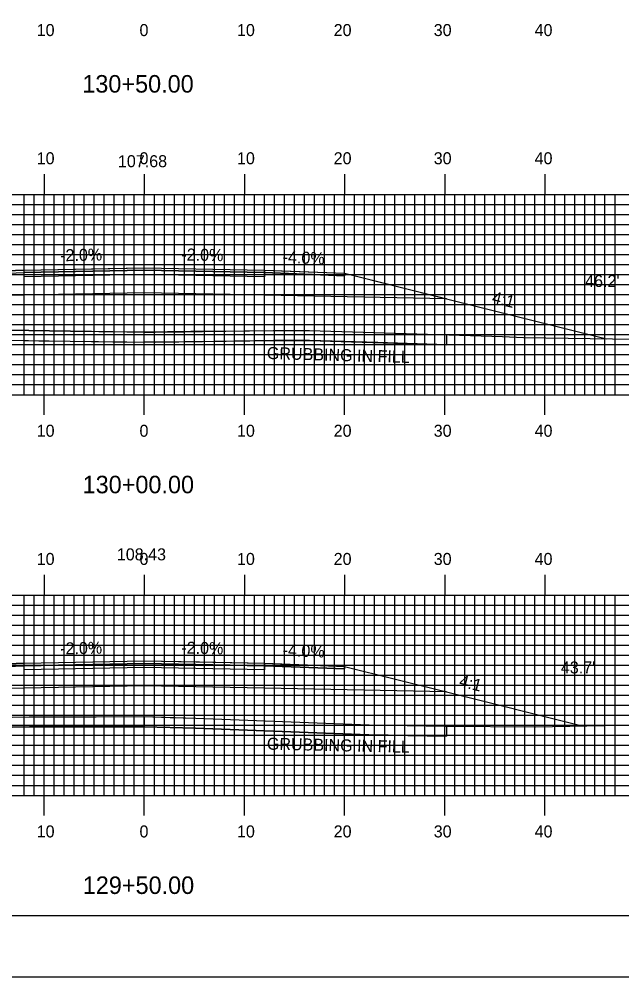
# Model space of a CAD drawing. Extents: x 1773990 to 1774333, y 442591 to 442811.
# Drawn here: x 1774143.2 to 1774203.3, y 442590.5 to 442686.2 of the extents above; entities that cross this region are included whole.
import ezdxf

# ---------------------------------------------------------------- set-up
doc = ezdxf.new("R2010")
doc.units = 0
for name, color, linetype in [('ANNOTATION', 7, 'Continuous'), ('BORDER', 7, 'Continuous'), ('D_Roadway_Centerline', 7, 'Continuous'), ('D_Roadway_Centerline_Text', 7, 'Continuous'), ('D_Roadway_Edge_Shoulder', 7, 'Continuous'), ('D_Roadway_Edge_TW', 7, 'Continuous'), ('D_Roadway_Pavement', 7, 'Continuous'), ('D_Roadway_SlopeLines', 7, 'Continuous'), ('D_Roadway_SubGrade', 7, 'Continuous'), ('D_Text_Standard', 7, 'Continuous'), ('GRUBBING IN FILL', 7, 'Continuous'), ('H_V ANNOTATION', 7, 'Continuous'), ('MAJOR', 7, 'Continuous'), ('MINOR', 7, 'Continuous'), ('PLOT BOUNDARY', 7, 'Continuous'), ('S_Roadway_Centerline', 7, 'Continuous')]:
    doc.layers.add(name, color=color, linetype=linetype)

msp = doc.modelspace()

# ---------------------------------------------------------------- linework, layer by layer
at = {"layer": 'BORDER'}
msp.add_lwpolyline([(1774006.059, 442596.665), (1774326.059, 442596.665), (1774326.059, 442806.665), (1774006.059, 442806.665)], close=True, dxfattribs=at)
at = {"layer": 'D_Roadway_Centerline'}
for points in [[(1774111.186, 442655.695), (1774121.01, 442658.151), (1774130.759, 442660.588), (1774143.659, 442661.104), (1774143.66, 442661.104), (1774152.062, 442661.272), (1774155.659, 442661.344), (1774167.659, 442661.104), (1774170.226, 442661.002), (1774175.659, 442660.784), (1774184.924, 442658.468), (1774185.833, 442658.24), (1774201.809, 442654.246), (1774201.81, 442654.246)], [(1774107.784, 442616.308), (1774117.905, 442618.838), (1774127.359, 442621.202), (1774143.659, 442621.854), (1774155.659, 442622.094), (1774161.174, 442621.984), (1774167.659, 442621.854), (1774171.953, 442621.682), (1774175.659, 442621.534), (1774185.833, 442618.99), (1774199.367, 442615.606)]]:
    msp.add_lwpolyline(points, dxfattribs=at)
at = {"layer": 'D_Roadway_Edge_Shoulder'}
for points in [[(1774143.659, 442661.104), (1774130.759, 442660.588), (1774130.759, 442660.338), (1774143.659, 442660.854)], [(1774167.659, 442661.104), (1774175.659, 442660.784), (1774175.659, 442660.534), (1774167.659, 442660.854)], [(1774143.659, 442621.854), (1774127.359, 442621.202), (1774127.359, 442620.952), (1774143.659, 442621.604)], [(1774167.659, 442621.854), (1774175.659, 442621.534), (1774175.659, 442621.284), (1774167.659, 442621.604)]]:
    msp.add_lwpolyline(points, close=True, dxfattribs=at)
at = {"layer": 'D_Roadway_Edge_TW'}
for points in [[(1774143.659, 442660.854), (1774143.659, 442661.104), (1774155.659, 442661.344), (1774167.659, 442661.104), (1774167.659, 442660.854), (1774155.659, 442661.094)], [(1774143.659, 442621.604), (1774143.659, 442621.854), (1774155.659, 442622.094), (1774167.659, 442621.854), (1774167.659, 442621.604), (1774155.659, 442621.844)]]:
    msp.add_lwpolyline(points, close=True, dxfattribs=at)
at = {"layer": 'D_Roadway_Pavement'}
for points in [[(1774143.659, 442660.437), (1774143.659, 442660.854), (1774155.659, 442661.094), (1774167.659, 442660.854), (1774167.659, 442660.437), (1774155.659, 442660.677)], [(1774143.659, 442621.187), (1774143.659, 442621.604), (1774155.659, 442621.844), (1774167.659, 442621.604), (1774167.659, 442621.187), (1774155.659, 442621.427)]]:
    msp.add_lwpolyline(points, close=True, dxfattribs=at)
at = {"layer": 'D_Roadway_SlopeLines'}
for points in [[(1774175.659, 442660.784), (1774185.833, 442658.24), (1774201.81, 442654.246)], [(1774175.659, 442621.534), (1774185.833, 442618.99), (1774199.367, 442615.606)]]:
    msp.add_lwpolyline(points, dxfattribs=at)
at = {"layer": 'D_Roadway_SubGrade'}
for points in [[(1774143.659, 442658.604), (1774121.01, 442658.151), (1774130.759, 442660.588), (1774130.759, 442660.338), (1774143.659, 442660.854), (1774155.659, 442661.094), (1774167.659, 442660.854), (1774175.659, 442660.534), (1774175.659, 442660.784), (1774185.833, 442658.24), (1774167.659, 442658.604), (1774155.659, 442658.844)], [(1774143.659, 442619.354), (1774117.905, 442618.838), (1774127.359, 442621.202), (1774127.359, 442620.952), (1774143.659, 442621.604), (1774155.659, 442621.844), (1774167.659, 442621.604), (1774175.659, 442621.284), (1774175.659, 442621.534), (1774185.833, 442618.99), (1774167.659, 442619.354), (1774155.659, 442619.594)]]:
    msp.add_lwpolyline(points, close=True, dxfattribs=at)
at = {"layer": 'GRUBBING IN FILL'}
for p, q in [((1774185.833, 442654.645), (1774185.833, 442653.644)), ((1774185.833, 442654.645), (1774185.833, 442653.644)), ((1774185.833, 442615.571), (1774185.833, 442614.569)), ((1774185.833, 442615.571), (1774185.833, 442614.569))]:
    msp.add_line(p, q, dxfattribs=at)
for points in [[(1774125.485, 442655.237), (1774125.485, 442654.211), (1774134.235, 442654.315), (1774138.123, 442654.206), (1774145.135, 442654.046), (1774148.26, 442653.994), (1774152.504, 442653.952), (1774155.659, 442653.921), (1774155.659, 442654.921), (1774152.509, 442654.952), (1774148.273, 442654.994), (1774142.032, 442655.097), (1774138.138, 442655.206), (1774134.243, 442655.315), (1774130.25, 442655.268), (1774126.257, 442655.22)], [(1774155.659, 442654.921), (1774156.746, 442654.91), (1774159.694, 442654.95), (1774162.642, 442654.99), (1774168.537, 442655.069), (1774172.16, 442655.082), (1774181.8, 442654.774), (1774185.833, 442654.645), (1774185.833, 442653.644), (1774178.988, 442653.863), (1774172.142, 442654.082), (1774168.548, 442654.069), (1774162.648, 442653.99), (1774156.748, 442653.91), (1774155.659, 442653.921)], [(1774155.659, 442654.921), (1774156.746, 442654.91), (1774159.694, 442654.95), (1774162.642, 442654.99), (1774168.537, 442655.069), (1774172.16, 442655.082), (1774181.8, 442654.774), (1774185.833, 442654.645), (1774185.833, 442653.644), (1774178.988, 442653.863), (1774172.142, 442654.082), (1774168.548, 442654.069), (1774162.648, 442653.99), (1774156.748, 442653.91), (1774155.659, 442653.921)], [(1774155.659, 442654.921), (1774156.746, 442654.91), (1774162.642, 442654.99)], [(1774155.659, 442654.921), (1774156.746, 442654.91), (1774162.642, 442654.99)], [(1774125.485, 442616.21), (1774132.101, 442616.307), (1774140.725, 442616.436), (1774144.174, 442616.491), (1774150.849, 442616.51), (1774155.659, 442616.523), (1774155.659, 442615.522), (1774150.852, 442615.51), (1774147.518, 442615.5), (1774144.183, 442615.491), (1774138.846, 442615.476), (1774134.703, 442615.344), (1774126.507, 442615.233), (1774125.485, 442615.21)], [(1774155.659, 442616.523), (1774158.25, 442616.443), (1774160.813, 442616.364), (1774169.463, 442616.039), (1774178.114, 442615.715), (1774185.833, 442615.571), (1774185.833, 442614.569), (1774181.959, 442614.642), (1774178.086, 442614.715), (1774169.432, 442615.04), (1774160.779, 442615.365), (1774155.659, 442615.522)], [(1774155.659, 442616.523), (1774158.25, 442616.443), (1774160.813, 442616.364), (1774169.463, 442616.039), (1774178.114, 442615.715), (1774185.833, 442615.571), (1774185.833, 442614.569), (1774181.959, 442614.642), (1774178.086, 442614.715), (1774169.432, 442615.04), (1774160.779, 442615.365), (1774155.659, 442615.522)]]:
    msp.add_lwpolyline(points, close=True, dxfattribs=at)
for points in [[(1774125.485, 442654.211), (1774134.235, 442654.315), (1774138.123, 442654.206), (1774145.135, 442654.046), (1774148.26, 442653.994), (1774152.504, 442653.952), (1774155.659, 442653.921), (1774155.659, 442654.921), (1774152.509, 442654.952), (1774148.273, 442654.994), (1774142.032, 442655.097), (1774138.138, 442655.206), (1774134.243, 442655.315), (1774130.25, 442655.268), (1774126.257, 442655.22), (1774125.485, 442655.237)], [(1774125.485, 442654.211), (1774134.235, 442654.315), (1774142.01, 442654.097), (1774148.26, 442653.994), (1774156.748, 442653.91), (1774168.548, 442654.069), (1774170.602, 442654.088), (1774172.142, 442654.082), (1774185.833, 442653.644)], [(1774125.485, 442654.211), (1774134.235, 442654.315), (1774142.01, 442654.097), (1774148.26, 442653.994), (1774156.748, 442653.91), (1774168.548, 442654.069), (1774170.602, 442654.088), (1774172.142, 442654.082), (1774185.833, 442653.644)], [(1774125.485, 442616.21), (1774132.101, 442616.307), (1774140.725, 442616.436), (1774144.174, 442616.491), (1774150.849, 442616.51), (1774155.659, 442616.523), (1774155.659, 442615.522), (1774150.852, 442615.51), (1774147.518, 442615.5), (1774144.183, 442615.491), (1774138.846, 442615.476), (1774134.703, 442615.344), (1774126.507, 442615.233), (1774125.485, 442615.21)], [(1774125.485, 442615.21), (1774127.529, 442615.255), (1774132.114, 442615.307), (1774137.292, 442615.382), (1774144.183, 442615.491), (1774150.852, 442615.51), (1774155.673, 442615.522), (1774160.779, 442615.365), (1774178.086, 442614.715), (1774185.833, 442614.569)], [(1774125.485, 442615.21), (1774127.529, 442615.255), (1774132.114, 442615.307), (1774137.292, 442615.382), (1774144.183, 442615.491), (1774150.852, 442615.51), (1774155.673, 442615.522), (1774160.779, 442615.365), (1774178.086, 442614.715), (1774185.833, 442614.569)]]:
    msp.add_lwpolyline(points, dxfattribs=at)
at = {"layer": 'MAJOR'}
for p, q in [((1774145.659, 442670.669), (1774145.659, 442668.665)), ((1774155.659, 442670.669), (1774155.659, 442668.665)), ((1774165.659, 442670.669), (1774165.659, 442668.665)), ((1774175.659, 442670.669), (1774175.659, 442668.665)), ((1774185.659, 442670.669), (1774185.659, 442668.665)), ((1774195.659, 442670.669), (1774195.659, 442668.665)), ((1774015.659, 442668.665), (1774295.659, 442668.665)), ((1774015.659, 442668.665), (1774295.659, 442668.665)), ((1774145.659, 442648.665), (1774145.659, 442668.665)), ((1774155.659, 442648.665), (1774155.659, 442668.665)), ((1774165.659, 442648.665), (1774165.659, 442668.665)), ((1774175.659, 442648.665), (1774175.659, 442668.665)), ((1774185.659, 442648.665), (1774185.659, 442668.665)), ((1774195.659, 442648.665), (1774195.659, 442668.665)), ((1774015.659, 442663.665), (1774295.659, 442663.665)), ((1774015.659, 442658.665), (1774295.659, 442658.665)), ((1774015.659, 442653.665), (1774295.659, 442653.665)), ((1774015.659, 442648.665), (1774295.659, 442648.665)), ((1774015.659, 442648.665), (1774295.659, 442648.665)), ((1774145.659, 442646.661), (1774145.659, 442648.665)), ((1774155.659, 442646.661), (1774155.659, 442648.665)), ((1774165.659, 442646.661), (1774165.659, 442648.665)), ((1774175.659, 442646.661), (1774175.659, 442648.665)), ((1774185.659, 442646.661), (1774185.659, 442648.665)), ((1774195.659, 442646.661), (1774195.659, 442648.665)), ((1774145.659, 442630.669), (1774145.659, 442628.665)), ((1774155.659, 442630.669), (1774155.659, 442628.665)), ((1774165.659, 442630.669), (1774165.659, 442628.665)), ((1774175.659, 442630.669), (1774175.659, 442628.665)), ((1774185.659, 442630.669), (1774185.659, 442628.665)), ((1774195.659, 442630.669), (1774195.659, 442628.665)), ((1774015.659, 442628.665), (1774295.659, 442628.665)), ((1774015.659, 442628.665), (1774295.659, 442628.665)), ((1774145.659, 442608.665), (1774145.659, 442628.665)), ((1774155.659, 442608.665), (1774155.659, 442628.665)), ((1774165.659, 442608.665), (1774165.659, 442628.665)), ((1774175.659, 442608.665), (1774175.659, 442628.665)), ((1774185.659, 442608.665), (1774185.659, 442628.665)), ((1774195.659, 442608.665), (1774195.659, 442628.665)), ((1774015.659, 442623.665), (1774295.659, 442623.665)), ((1774015.659, 442618.665), (1774295.659, 442618.665)), ((1774015.659, 442613.665), (1774295.659, 442613.665)), ((1774015.659, 442608.665), (1774295.659, 442608.665)), ((1774015.659, 442608.665), (1774295.659, 442608.665)), ((1774145.659, 442606.661), (1774145.659, 442608.665)), ((1774155.659, 442606.661), (1774155.659, 442608.665)), ((1774165.659, 442606.661), (1774165.659, 442608.665)), ((1774175.659, 442606.661), (1774175.659, 442608.665)), ((1774185.659, 442606.661), (1774185.659, 442608.665)), ((1774195.659, 442606.661), (1774195.659, 442608.665))]:
    msp.add_line(p, q, dxfattribs=at)
at = {"layer": 'MINOR'}
for p, q in [((1774143.659, 442648.665), (1774143.659, 442668.665)), ((1774144.659, 442648.665), (1774144.659, 442668.665)), ((1774146.659, 442648.665), (1774146.659, 442668.665)), ((1774147.659, 442648.665), (1774147.659, 442668.665)), ((1774148.659, 442648.665), (1774148.659, 442668.665)), ((1774149.659, 442648.665), (1774149.659, 442668.665)), ((1774150.659, 442648.665), (1774150.659, 442668.665)), ((1774151.659, 442648.665), (1774151.659, 442668.665)), ((1774152.659, 442648.665), (1774152.659, 442668.665)), ((1774153.659, 442648.665), (1774153.659, 442668.665)), ((1774154.659, 442648.665), (1774154.659, 442668.665)), ((1774156.659, 442648.665), (1774156.659, 442668.665)), ((1774157.659, 442648.665), (1774157.659, 442668.665)), ((1774158.659, 442648.665), (1774158.659, 442668.665)), ((1774159.659, 442648.665), (1774159.659, 442668.665)), ((1774160.659, 442648.665), (1774160.659, 442668.665)), ((1774161.659, 442648.665), (1774161.659, 442668.665)), ((1774162.659, 442648.665), (1774162.659, 442668.665)), ((1774163.659, 442648.665), (1774163.659, 442668.665)), ((1774164.659, 442648.665), (1774164.659, 442668.665)), ((1774166.659, 442648.665), (1774166.659, 442668.665)), ((1774167.659, 442648.665), (1774167.659, 442668.665)), ((1774168.659, 442648.665), (1774168.659, 442668.665)), ((1774169.659, 442648.665), (1774169.659, 442668.665)), ((1774170.659, 442648.665), (1774170.659, 442668.665)), ((1774171.659, 442648.665), (1774171.659, 442668.665)), ((1774172.659, 442648.665), (1774172.659, 442668.665)), ((1774173.659, 442648.665), (1774173.659, 442668.665)), ((1774174.659, 442648.665), (1774174.659, 442668.665)), ((1774176.659, 442648.665), (1774176.659, 442668.665)), ((1774177.659, 442648.665), (1774177.659, 442668.665)), ((1774178.659, 442648.665), (1774178.659, 442668.665)), ((1774179.659, 442648.665), (1774179.659, 442668.665)), ((1774180.659, 442648.665), (1774180.659, 442668.665)), ((1774181.659, 442648.665), (1774181.659, 442668.665)), ((1774182.659, 442648.665), (1774182.659, 442668.665)), ((1774183.659, 442648.665), (1774183.659, 442668.665)), ((1774184.659, 442648.665), (1774184.659, 442668.665)), ((1774186.659, 442648.665), (1774186.659, 442668.665)), ((1774187.659, 442648.665), (1774187.659, 442668.665)), ((1774188.659, 442648.665), (1774188.659, 442668.665)), ((1774189.659, 442648.665), (1774189.659, 442668.665)), ((1774190.659, 442648.665), (1774190.659, 442668.665)), ((1774191.659, 442648.665), (1774191.659, 442668.665)), ((1774192.659, 442648.665), (1774192.659, 442668.665)), ((1774193.659, 442648.665), (1774193.659, 442668.665)), ((1774194.659, 442648.665), (1774194.659, 442668.665)), ((1774196.659, 442648.665), (1774196.659, 442668.665)), ((1774197.659, 442648.665), (1774197.659, 442668.665)), ((1774198.659, 442648.665), (1774198.659, 442668.665)), ((1774199.659, 442648.665), (1774199.659, 442668.665)), ((1774200.659, 442648.665), (1774200.659, 442668.665)), ((1774201.659, 442648.665), (1774201.659, 442668.665)), ((1774202.659, 442648.665), (1774202.659, 442668.665)), ((1774015.659, 442667.665), (1774295.659, 442667.665)), ((1774015.659, 442666.665), (1774295.659, 442666.665)), ((1774015.659, 442665.665), (1774295.659, 442665.665)), ((1774015.659, 442664.665), (1774295.659, 442664.665)), ((1774015.659, 442662.665), (1774295.659, 442662.665)), ((1774015.659, 442661.665), (1774295.659, 442661.665)), ((1774015.659, 442660.665), (1774295.659, 442660.665)), ((1774015.659, 442659.665), (1774295.659, 442659.665)), ((1774015.659, 442657.665), (1774295.659, 442657.665)), ((1774015.659, 442656.665), (1774295.659, 442656.665)), ((1774015.659, 442655.665), (1774295.659, 442655.665)), ((1774015.659, 442654.665), (1774295.659, 442654.665)), ((1774015.659, 442652.665), (1774295.659, 442652.665)), ((1774015.659, 442651.665), (1774295.659, 442651.665)), ((1774015.659, 442650.665), (1774295.659, 442650.665)), ((1774015.659, 442649.665), (1774295.659, 442649.665)), ((1774143.659, 442608.665), (1774143.659, 442628.665)), ((1774144.659, 442608.665), (1774144.659, 442628.665)), ((1774146.659, 442608.665), (1774146.659, 442628.665)), ((1774147.659, 442608.665), (1774147.659, 442628.665)), ((1774148.659, 442608.665), (1774148.659, 442628.665)), ((1774149.659, 442608.665), (1774149.659, 442628.665)), ((1774150.659, 442608.665), (1774150.659, 442628.665)), ((1774151.659, 442608.665), (1774151.659, 442628.665)), ((1774152.659, 442608.665), (1774152.659, 442628.665)), ((1774153.659, 442608.665), (1774153.659, 442628.665)), ((1774154.659, 442608.665), (1774154.659, 442628.665)), ((1774156.659, 442608.665), (1774156.659, 442628.665)), ((1774157.659, 442608.665), (1774157.659, 442628.665)), ((1774158.659, 442608.665), (1774158.659, 442628.665)), ((1774159.659, 442608.665), (1774159.659, 442628.665)), ((1774160.659, 442608.665), (1774160.659, 442628.665)), ((1774161.659, 442608.665), (1774161.659, 442628.665)), ((1774162.659, 442608.665), (1774162.659, 442628.665)), ((1774163.659, 442608.665), (1774163.659, 442628.665)), ((1774164.659, 442608.665), (1774164.659, 442628.665)), ((1774166.659, 442608.665), (1774166.659, 442628.665)), ((1774167.659, 442608.665), (1774167.659, 442628.665)), ((1774168.659, 442608.665), (1774168.659, 442628.665)), ((1774169.659, 442608.665), (1774169.659, 442628.665)), ((1774170.659, 442608.665), (1774170.659, 442628.665)), ((1774171.659, 442608.665), (1774171.659, 442628.665)), ((1774172.659, 442608.665), (1774172.659, 442628.665)), ((1774173.659, 442608.665), (1774173.659, 442628.665)), ((1774174.659, 442608.665), (1774174.659, 442628.665)), ((1774176.659, 442608.665), (1774176.659, 442628.665)), ((1774177.659, 442608.665), (1774177.659, 442628.665)), ((1774178.659, 442608.665), (1774178.659, 442628.665)), ((1774179.659, 442608.665), (1774179.659, 442628.665)), ((1774180.659, 442608.665), (1774180.659, 442628.665)), ((1774181.659, 442608.665), (1774181.659, 442628.665)), ((1774182.659, 442608.665), (1774182.659, 442628.665)), ((1774183.659, 442608.665), (1774183.659, 442628.665)), ((1774184.659, 442608.665), (1774184.659, 442628.665)), ((1774186.659, 442608.665), (1774186.659, 442628.665)), ((1774187.659, 442608.665), (1774187.659, 442628.665)), ((1774188.659, 442608.665), (1774188.659, 442628.665)), ((1774189.659, 442608.665), (1774189.659, 442628.665)), ((1774190.659, 442608.665), (1774190.659, 442628.665)), ((1774191.659, 442608.665), (1774191.659, 442628.665)), ((1774192.659, 442608.665), (1774192.659, 442628.665)), ((1774193.659, 442608.665), (1774193.659, 442628.665)), ((1774194.659, 442608.665), (1774194.659, 442628.665)), ((1774196.659, 442608.665), (1774196.659, 442628.665)), ((1774197.659, 442608.665), (1774197.659, 442628.665)), ((1774198.659, 442608.665), (1774198.659, 442628.665)), ((1774199.659, 442608.665), (1774199.659, 442628.665)), ((1774200.659, 442608.665), (1774200.659, 442628.665)), ((1774201.659, 442608.665), (1774201.659, 442628.665)), ((1774202.659, 442608.665), (1774202.659, 442628.665)), ((1774015.659, 442627.665), (1774295.659, 442627.665)), ((1774015.659, 442626.665), (1774295.659, 442626.665)), ((1774015.659, 442625.665), (1774295.659, 442625.665)), ((1774015.659, 442624.665), (1774295.659, 442624.665)), ((1774015.659, 442622.665), (1774295.659, 442622.665)), ((1774015.659, 442621.665), (1774295.659, 442621.665)), ((1774015.659, 442620.665), (1774295.659, 442620.665)), ((1774015.659, 442619.665), (1774295.659, 442619.665)), ((1774015.659, 442617.665), (1774295.659, 442617.665)), ((1774015.659, 442616.665), (1774295.659, 442616.665)), ((1774015.659, 442615.665), (1774295.659, 442615.665)), ((1774015.659, 442614.665), (1774295.659, 442614.665)), ((1774015.659, 442612.665), (1774295.659, 442612.665)), ((1774015.659, 442611.665), (1774295.659, 442611.665)), ((1774015.659, 442610.665), (1774295.659, 442610.665)), ((1774015.659, 442609.665), (1774295.659, 442609.665))]:
    msp.add_line(p, q, dxfattribs=at)
at = {"layer": 'PLOT BOUNDARY'}
msp.add_lwpolyline([(1773989.872, 442590.547), (1774329.872, 442590.547), (1774329.872, 442810.547), (1773989.872, 442810.547)], close=True, dxfattribs=at)
at = {"layer": 'S_Roadway_Centerline'}
for points in [[(1774015.659, 442657.229), (1774029.156, 442656.948), (1774037.11, 442656.928), (1774041.73, 442656.856), (1774046.169, 442656.612), (1774058.455, 442656.465), (1774070.608, 442656.245), (1774076.731, 442656.201), (1774082.317, 442655.875), (1774094.599, 442655.94), (1774103.95, 442655.992), (1774118.873, 442655.379), (1774126.257, 442655.22), (1774134.243, 442655.315), (1774142.032, 442655.097), (1774148.273, 442654.994), (1774156.746, 442654.91), (1774168.537, 442655.069), (1774170.6, 442655.088), (1774172.16, 442655.082), (1774191.439, 442654.465), (1774193.508, 442654.378), (1774213.524, 442654.06)], [(1774088.493, 442616.632), (1774105.299, 442616.428), (1774108.99, 442616.25), (1774112.564, 442616.247), (1774120.185, 442616.092), (1774127.512, 442616.255), (1774132.101, 442616.307), (1774137.277, 442616.382), (1774144.174, 442616.491), (1774150.849, 442616.51), (1774155.687, 442616.522), (1774160.813, 442616.364), (1774178.114, 442615.715), (1774185.703, 442615.571), (1774194.728, 442615.518), (1774210.121, 442615.813)]]:
    msp.add_lwpolyline(points, dxfattribs=at)

# ---------------------------------------------------------------- texts
at = {"layer": 'ANNOTATION'}
for s, rotation, p in [('-2.0%', 1.14579, (1774147.266, 442661.977)), ('-2.0%', 358.85417, (1774159.345, 442662.071)), ('-4.0%', 357.70946, (1774169.451, 442661.834)), ('4:1', 345.96145, (1774190.3, 442657.851)), ('-2.0%', 1.14571, (1774147.265, 442622.727)), ('-2.0%', 358.85422, (1774159.345, 442622.821)), ('-4.0%', 357.70935, (1774169.451, 442622.584)), ('4:1', 345.96149, (1774187.019, 442619.555))]:
    msp.add_text(s, height=1.2, rotation=rotation, dxfattribs=at).set_placement(p)
at = {"layer": 'D_Roadway_Centerline'}
for s, p in [('C', (1774155.654, 442661.344)), ('L', (1774155.659, 442661.337)), ('C', (1774155.654, 442622.094)), ('L', (1774155.659, 442622.087))]:
    msp.add_text(s, height=0.0146, dxfattribs=at).set_placement(p)
at = {"layer": 'D_Roadway_Centerline_Text'}
for s, p in [('107.68', (1774153.021, 442671.374)), ('108.43', (1774152.914, 442632.124))]:
    msp.add_text(s, height=1.2, dxfattribs=at).set_placement(p)
at = {"layer": 'D_Text_Standard'}
for s, p in [("46.2'", (1774199.676, 442659.416)), ("43.7'", (1774197.252, 442620.833))]:
    msp.add_text(s, height=1.2, dxfattribs=at).set_placement(p)
at = {"layer": 'GRUBBING IN FILL'}
for rotation, p in [(358.37507, (1774167.881, 442652.234)), (358.6879, (1774167.888, 442613.235))]:
    msp.add_text('GRUBBING IN FILL', height=1.2, rotation=rotation, dxfattribs=at).set_placement(p)
at = {"layer": 'H_V ANNOTATION'}
for s, height, p in [('10', 1.2, (1774144.91, 442684.465)), ('0', 1.2, (1774155.177, 442684.465)), ('10', 1.2, (1774164.91, 442684.465)), ('20', 1.2, (1774174.567, 442684.465)), ('30', 1.2, (1774184.556, 442684.465)), ('40', 1.2, (1774194.631, 442684.465)), ('130+50.00', 1.75, (1774149.463, 442678.821)), ('10', 1.2, (1774144.91, 442671.665)), ('0', 1.2, (1774155.177, 442671.665)), ('10', 1.2, (1774164.91, 442671.665)), ('20', 1.2, (1774174.567, 442671.665)), ('30', 1.2, (1774184.556, 442671.665)), ('40', 1.2, (1774194.631, 442671.665)), ('10', 1.2, (1774144.91, 442644.465)), ('0', 1.2, (1774155.177, 442644.465)), ('10', 1.2, (1774164.91, 442644.465)), ('20', 1.2, (1774174.567, 442644.465)), ('30', 1.2, (1774184.556, 442644.465)), ('40', 1.2, (1774194.631, 442644.465)), ('130+00.00', 1.75, (1774149.495, 442638.821)), ('10', 1.2, (1774144.91, 442631.665)), ('0', 1.2, (1774155.177, 442631.665)), ('10', 1.2, (1774164.91, 442631.665)), ('20', 1.2, (1774174.567, 442631.665)), ('30', 1.2, (1774184.556, 442631.665)), ('40', 1.2, (1774194.631, 442631.665)), ('10', 1.2, (1774144.91, 442604.465)), ('0', 1.2, (1774155.177, 442604.465)), ('10', 1.2, (1774164.91, 442604.465)), ('20', 1.2, (1774174.567, 442604.465)), ('30', 1.2, (1774184.556, 442604.465)), ('40', 1.2, (1774194.631, 442604.465)), ('129+50.00', 1.75, (1774149.51, 442598.821))]:
    msp.add_text(s, height=height, dxfattribs=at).set_placement(p)

doc.saveas('drawing.dxf')
